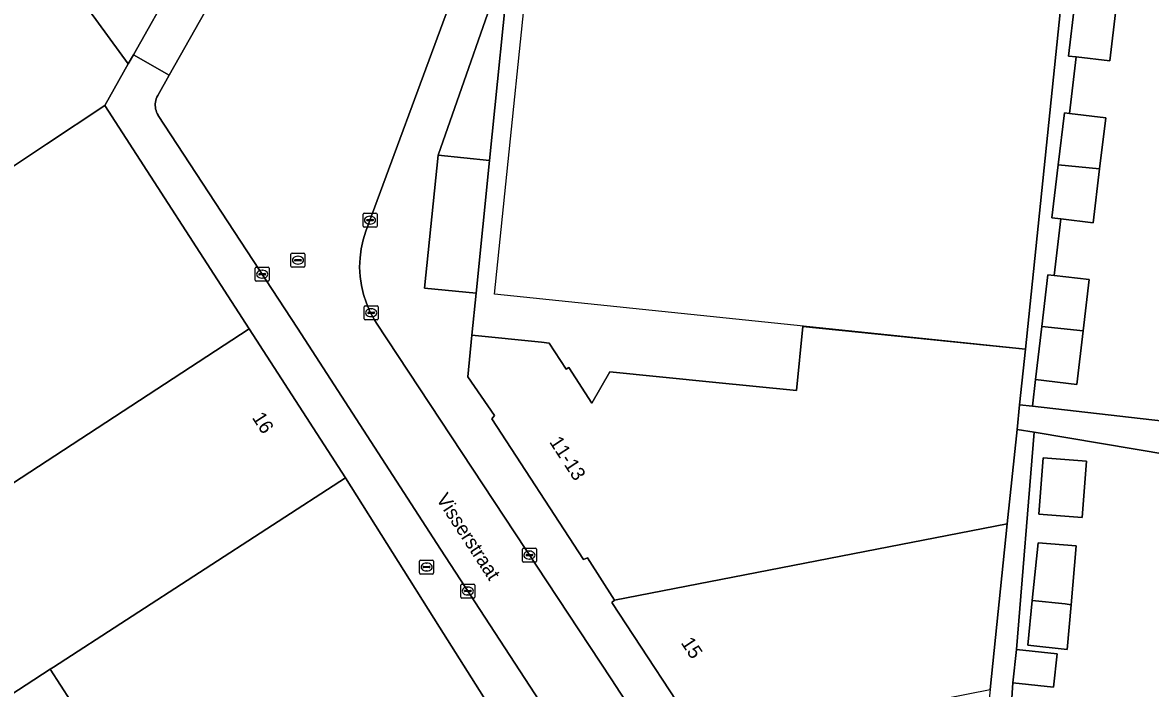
# Model space of a CAD drawing. Extents: x 160856 to 161310, y 384024 to 384878.
# Drawn here: x 161076.4 to 161157.1, y 384511.2 to 384558.9 of the extents above; entities that cross this region are included whole.
import ezdxf

# ---------------------------------------------------------------- set-up
doc = ezdxf.new("R2010")
doc.units = 0
for name, color, linetype in [('IMGEO_Brandkraan', 7, 'Continuous'), ('IMGEO_Erf', 7, 'Continuous'), ('IMGEO_Kolk', 7, 'Continuous'), ('IMGEO_Muur', 7, 'Continuous'), ('IMGEO_Openbare_ruimte_label', 7, 'Continuous'), ('IMGEO_Pand', 7, 'Continuous'), ('IMGEO_Pand_nummerreeks', 7, 'Continuous'), ('IMGEO_Pand_vergunning_verleend', 7, 'Continuous'), ('IMGEO_Parkeervlak_open', 7, 'Continuous'), ('IMGEO_Rijbaan_lokaal_open', 7, 'Continuous'), ('IMGEO_Rioolput', 7, 'Continuous'), ('IMGEO_Voetpad_open', 7, 'Continuous')]:
    doc.layers.add(name, color=color, linetype=linetype)

msp = doc.modelspace()

# ---------------------------------------------------------------- linework, layer by layer
at = {"layer": 'IMGEO_Brandkraan'}
for p, q in [((161104.842, 384519.474), (161104.842, 384520.326)), ((161104.917, 384520.4), (161105.769, 384520.4)), ((161105.33, 384520.18), (161105.355, 384520.18)), ((161105.843, 384520.326), (161105.843, 384519.474)), ((161105.769, 384519.4), (161104.917, 384519.4)), ((161105.101, 384519.894), (161105.101, 384519.906)), ((161105.539, 384519.857), (161105.141, 384519.857)), ((161105.144, 384519.943), (161105.542, 384519.943)), ((161105.353, 384519.62), (161105.328, 384519.62)), ((161105.585, 384519.906), (161105.585, 384519.894))]:
    msp.add_line(p, q, dxfattribs=at)
for points in [[(161104.842, 384519.474), (161104.842, 384520.326)], [(161104.917, 384520.4), (161105.769, 384520.4)], [(161105.843, 384520.326), (161105.843, 384519.474)], [(161105.769, 384519.4), (161104.917, 384519.4)]]:
    msp.add_lwpolyline(points, dxfattribs=at)
for centre, radius, start, end in [((161104.919, 384520.324), 0.0765, 91.55205, 178.44795), ((161104.919, 384520.324), 0.0765, 91.55205, 178.44795), ((161105.767, 384520.324), 0.0765, 1.55205, 88.44795), ((161105.767, 384520.324), 0.0765, 1.55205, 88.44795), ((161104.919, 384519.476), 0.0765, 181.55205, 268.44795), ((161104.919, 384519.476), 0.0765, 181.55205, 268.44795), ((161105.141, 384519.903), 0.0403, 85.87752, 175.75265), ((161105.138, 384519.893), 0.0366, 178.93798, 274.71019), ((161105.542, 384519.9), 0.043, 264.86636, 352.45326), ((161105.546, 384519.905), 0.0386, 1.73085, 96.63898), ((161105.767, 384519.476), 0.0765, 271.55205, 358.44795), ((161105.767, 384519.476), 0.0765, 271.55205, 358.44795)]:
    msp.add_arc(centre, radius, start, end, dxfattribs=at)
for centre, major_axis, ratio, start_param, end_param in [((161105.329, 384519.9), (-0.387, 0.002), 0.722429, 4.712389, 7.853982), ((161105.354, 384519.9), (-0.39, 0.002), 0.717154, 1.570796, 4.712389)]:
    msp.add_ellipse(centre, major_axis=major_axis, ratio=ratio, start_param=start_param, end_param=end_param, dxfattribs=at)
at = {"layer": 'IMGEO_Erf'}
for points in [[(161151.278, 384565.385), (161119.159, 384568.638), (161113.261, 384569.256), (161111.404, 384564.308), (161109.851, 384548.986), (161108.888, 384539.484), (161108.586, 384536.5), (161113.56, 384535.984), (161114.109, 384535.927), (161115.335, 384534.049), (161115.518, 384534.168), (161117.174, 384531.631), (161118.462, 384533.867), (161125.805, 384533.126), (161131.806, 384532.52), (161132.272, 384537.113), (161148.189, 384535.497)], [(161149.148, 384523.684), (161149.461, 384527.721), (161152.575, 384527.48), (161152.263, 384523.443)], [(161109.703, 384510.154), (161106.274, 384515.593), (161099.532, 384526.285), (161078.632, 384512.731), (161078.403, 384512.582), (161086.528, 384500), (161089.266, 384495.761), (161093.508, 384498.519), (161093.22, 384498.961), (161094.818, 384500), (161104.086, 384506.027), (161103.703, 384506.616), (161103.966, 384506.787), (161104.133, 384506.531)], [(161151.459, 384517.196), (161151.179, 384513.998), (161148.36, 384514.309), (161148.683, 384517.506), (161149.099, 384521.62), (161151.828, 384521.418)]]:
    msp.add_lwpolyline(points, close=True, dxfattribs=at)
for points in [[(161154.683, 384559.954), (161154.228, 384556.109), (161151.831, 384556.393), (161151.352, 384552.341), (161153.94, 384552.035), (161153.507, 384548.38), (161153.052, 384544.535), (161150.736, 384544.809), (161150.256, 384540.757), (161152.763, 384540.46), (161152.33, 384536.804), (161151.875, 384532.96), (161148.919, 384533.31), (161148.694, 384531.411), (161164.334, 384529.618)], [(161163.276, 384527.128), (161148.815, 384529.545), (161147.564, 384514.007), (161150.475, 384513.686), (161150.211, 384511.294), (161147.3, 384511.615), (161147.199, 384510.164), (161149.928, 384509.962), (161149.557, 384505.722), (161149.279, 384502.542), (161146.46, 384502.853), (161144.606, 384486.647), (161147.568, 384486.405), (161147.279, 384482.873), (161144.317, 384483.115), (161144.28, 384482.884), (161157.474, 384480.784)]]:
    msp.add_lwpolyline(points, dxfattribs=at)
at = {"layer": 'IMGEO_Kolk'}
for p, q in [((161100.794, 384544.292), (161100.794, 384545.144)), ((161100.869, 384545.218), (161101.721, 384545.218)), ((161101.795, 384545.144), (161101.795, 384544.292)), ((161101.053, 384544.712), (161101.053, 384544.724)), ((161101.491, 384544.675), (161101.093, 384544.675)), ((161101.096, 384544.761), (161101.494, 384544.761)), ((161101.305, 384544.438), (161101.28, 384544.438)), ((161101.282, 384544.998), (161101.307, 384544.998)), ((161101.537, 384544.724), (161101.537, 384544.712)), ((161101.721, 384544.218), (161100.869, 384544.218)), ((161093.078, 384540.423), (161093.078, 384541.275)), ((161093.153, 384541.349), (161094.005, 384541.349)), ((161093.566, 384541.129), (161093.591, 384541.129)), ((161094.079, 384541.275), (161094.079, 384540.423)), ((161094.005, 384540.349), (161093.153, 384540.349)), ((161093.337, 384540.843), (161093.337, 384540.855)), ((161093.775, 384540.806), (161093.377, 384540.806)), ((161093.38, 384540.892), (161093.778, 384540.892)), ((161093.589, 384540.569), (161093.564, 384540.569)), ((161093.821, 384540.855), (161093.821, 384540.843)), ((161100.877, 384537.666), (161100.877, 384538.518)), ((161100.952, 384538.592), (161101.804, 384538.592)), ((161101.136, 384538.086), (161101.136, 384538.098)), ((161101.574, 384538.049), (161101.176, 384538.049)), ((161101.179, 384538.135), (161101.577, 384538.135)), ((161101.365, 384538.372), (161101.39, 384538.372)), ((161101.62, 384538.098), (161101.62, 384538.086)), ((161101.878, 384538.518), (161101.878, 384537.666)), ((161101.804, 384537.592), (161100.952, 384537.592)), ((161101.388, 384537.812), (161101.363, 384537.812)), ((161112.2, 384520.328), (161112.2, 384521.18)), ((161112.275, 384521.254), (161113.127, 384521.254)), ((161112.688, 384521.034), (161112.713, 384521.034)), ((161113.201, 384521.18), (161113.201, 384520.328)), ((161113.127, 384520.254), (161112.275, 384520.254)), ((161112.459, 384520.748), (161112.459, 384520.76)), ((161112.897, 384520.711), (161112.499, 384520.711)), ((161112.502, 384520.797), (161112.9, 384520.797)), ((161112.711, 384520.474), (161112.686, 384520.474)), ((161112.943, 384520.76), (161112.943, 384520.748)), ((161107.791, 384517.756), (161107.791, 384518.608)), ((161107.866, 384518.682), (161108.718, 384518.682)), ((161108.792, 384518.608), (161108.792, 384517.756)), ((161108.05, 384518.176), (161108.05, 384518.188)), ((161108.488, 384518.139), (161108.09, 384518.139)), ((161108.093, 384518.225), (161108.491, 384518.225)), ((161108.302, 384517.902), (161108.277, 384517.902)), ((161108.279, 384518.462), (161108.304, 384518.462)), ((161108.534, 384518.188), (161108.534, 384518.176)), ((161108.718, 384517.682), (161107.866, 384517.682))]:
    msp.add_line(p, q, dxfattribs=at)
for points in [[(161100.794, 384544.292), (161100.794, 384545.144)], [(161100.869, 384545.218), (161101.721, 384545.218)], [(161101.795, 384545.144), (161101.795, 384544.292)], [(161101.721, 384544.218), (161100.869, 384544.218)], [(161093.078, 384540.423), (161093.078, 384541.275)], [(161093.153, 384541.349), (161094.005, 384541.349)], [(161094.079, 384541.275), (161094.079, 384540.423)], [(161094.005, 384540.349), (161093.153, 384540.349)], [(161100.877, 384537.666), (161100.877, 384538.518)], [(161100.952, 384538.592), (161101.804, 384538.592)], [(161101.878, 384538.518), (161101.878, 384537.666)], [(161101.804, 384537.592), (161100.952, 384537.592)], [(161112.2, 384520.328), (161112.2, 384521.18)], [(161112.275, 384521.254), (161113.127, 384521.254)], [(161113.201, 384521.18), (161113.201, 384520.328)], [(161113.127, 384520.254), (161112.275, 384520.254)], [(161107.791, 384517.756), (161107.791, 384518.608)], [(161107.866, 384518.682), (161108.718, 384518.682)], [(161108.792, 384518.608), (161108.792, 384517.756)], [(161108.718, 384517.682), (161107.866, 384517.682)]]:
    msp.add_lwpolyline(points, dxfattribs=at)
for centre, radius, start, end in [((161100.871, 384545.142), 0.0765, 91.55205, 178.44795), ((161100.871, 384545.142), 0.0765, 91.55205, 178.44795), ((161101.719, 384545.142), 0.0765, 1.55205, 88.44795), ((161101.719, 384545.142), 0.0765, 1.55205, 88.44795), ((161101.093, 384544.721), 0.0403, 85.87752, 175.75265), ((161101.09, 384544.711), 0.0366, 178.93798, 274.71019), ((161101.494, 384544.718), 0.043, 264.86636, 352.45326), ((161101.498, 384544.723), 0.0386, 1.73085, 96.63898), ((161100.871, 384544.294), 0.0765, 181.55205, 268.44795), ((161100.871, 384544.294), 0.0765, 181.55205, 268.44795), ((161101.719, 384544.294), 0.0765, 271.55205, 358.44795), ((161101.719, 384544.294), 0.0765, 271.55205, 358.44795), ((161093.155, 384541.273), 0.0765, 91.55205, 178.44795), ((161093.155, 384541.273), 0.0765, 91.55205, 178.44795), ((161094.003, 384541.273), 0.0765, 1.55205, 88.44795), ((161094.003, 384541.273), 0.0765, 1.55205, 88.44795), ((161093.155, 384540.425), 0.0765, 181.55205, 268.44795), ((161093.155, 384540.425), 0.0765, 181.55205, 268.44795), ((161093.377, 384540.852), 0.0403, 85.87752, 175.75265), ((161093.374, 384540.842), 0.0366, 178.93798, 274.71019), ((161093.778, 384540.849), 0.043, 264.86636, 352.45326), ((161093.782, 384540.854), 0.0386, 1.73085, 96.63898), ((161094.003, 384540.425), 0.0765, 271.55205, 358.44795), ((161094.003, 384540.425), 0.0765, 271.55205, 358.44795), ((161100.954, 384538.516), 0.0765, 91.55205, 178.44795), ((161100.954, 384538.516), 0.0765, 91.55205, 178.44795), ((161101.176, 384538.095), 0.0403, 85.87752, 175.75265), ((161101.173, 384538.085), 0.0366, 178.93798, 274.71019), ((161101.577, 384538.092), 0.043, 264.86636, 352.45326), ((161101.581, 384538.097), 0.0386, 1.73085, 96.63898), ((161101.802, 384538.516), 0.0765, 1.55205, 88.44795), ((161101.802, 384538.516), 0.0765, 1.55205, 88.44795), ((161100.954, 384537.668), 0.0765, 181.55205, 268.44795), ((161100.954, 384537.668), 0.0765, 181.55205, 268.44795), ((161101.802, 384537.668), 0.0765, 271.55205, 358.44795), ((161101.802, 384537.668), 0.0765, 271.55205, 358.44795), ((161112.277, 384521.178), 0.0765, 91.55205, 178.44795), ((161112.277, 384521.178), 0.0765, 91.55205, 178.44795), ((161113.125, 384521.178), 0.0765, 1.55205, 88.44795), ((161113.125, 384521.178), 0.0765, 1.55205, 88.44795), ((161112.277, 384520.33), 0.0765, 181.55205, 268.44795), ((161112.277, 384520.33), 0.0765, 181.55205, 268.44795), ((161112.499, 384520.757), 0.0403, 85.87752, 175.75265), ((161112.496, 384520.747), 0.0366, 178.93798, 274.71019), ((161112.9, 384520.754), 0.043, 264.86636, 352.45326), ((161112.904, 384520.759), 0.0386, 1.73085, 96.63898), ((161113.125, 384520.33), 0.0765, 271.55205, 358.44795), ((161113.125, 384520.33), 0.0765, 271.55205, 358.44795), ((161107.868, 384518.606), 0.0765, 91.55205, 178.44795), ((161107.868, 384518.606), 0.0765, 91.55205, 178.44795), ((161108.716, 384518.606), 0.0765, 1.55205, 88.44795), ((161108.716, 384518.606), 0.0765, 1.55205, 88.44795), ((161107.868, 384517.758), 0.0765, 181.55205, 268.44795), ((161107.868, 384517.758), 0.0765, 181.55205, 268.44795), ((161108.09, 384518.185), 0.0403, 85.87752, 175.75265), ((161108.087, 384518.175), 0.0366, 178.93798, 274.71019), ((161108.491, 384518.182), 0.043, 264.86636, 352.45326), ((161108.495, 384518.187), 0.0386, 1.73085, 96.63898), ((161108.716, 384517.758), 0.0765, 271.55205, 358.44795), ((161108.716, 384517.758), 0.0765, 271.55205, 358.44795)]:
    msp.add_arc(centre, radius, start, end, dxfattribs=at)
for centre, major_axis, ratio, start_param, end_param in [((161101.281, 384544.718), (-0.387, 0.002), 0.722429, 4.712389, 7.853982), ((161101.306, 384544.718), (-0.39, 0.002), 0.717154, 1.570796, 4.712389), ((161093.565, 384540.849), (-0.387, 0.002), 0.722429, 4.712389, 7.853982), ((161093.59, 384540.849), (-0.39, 0.002), 0.717154, 1.570796, 4.712389), ((161101.364, 384538.092), (-0.387, 0.002), 0.722429, 4.712389, 7.853982), ((161101.389, 384538.092), (-0.39, 0.002), 0.717154, 1.570796, 4.712389), ((161112.687, 384520.754), (-0.387, 0.002), 0.722429, 4.712389, 7.853982), ((161112.712, 384520.754), (-0.39, 0.002), 0.717154, 1.570796, 4.712389), ((161108.278, 384518.182), (-0.387, 0.002), 0.722429, 4.712389, 7.853982), ((161108.303, 384518.182), (-0.39, 0.002), 0.717154, 1.570796, 4.712389)]:
    msp.add_ellipse(centre, major_axis=major_axis, ratio=ratio, start_param=start_param, end_param=end_param, dxfattribs=at)
at = {"layer": 'IMGEO_Muur'}
msp.add_lwpolyline([(161099.532, 384526.285), (161106.274, 384515.593)], dxfattribs=at)
at = {"layer": 'IMGEO_Pand'}
for points in [[(161154.683, 384559.954), (161151.722, 384560.255), (161151.272, 384556.459), (161151.831, 384556.393), (161154.228, 384556.109)], [(161061.847, 384516.849), (161092.65, 384536.939), (161082.319, 384552.931), (161078.154, 384550.165), (161074.251, 384547.573), (161050.778, 384531.991)], [(161153.94, 384552.035), (161151.352, 384552.341), (161150.984, 384552.385), (161150.546, 384548.681), (161153.507, 384548.38)], [(161153.507, 384548.38), (161150.546, 384548.681), (161150.096, 384544.885), (161150.736, 384544.809), (161153.052, 384544.535)], [(161152.763, 384540.46), (161150.256, 384540.757), (161149.807, 384540.81), (161149.369, 384537.105), (161152.33, 384536.804)], [(161147.778, 384531.516), (161148.189, 384535.497), (161132.272, 384537.113), (161131.806, 384532.52), (161125.805, 384533.126), (161118.462, 384533.867), (161117.174, 384531.631), (161115.518, 384534.168), (161115.335, 384534.049), (161114.109, 384535.927), (161113.56, 384535.984), (161108.586, 384536.5), (161108.284, 384533.515), (161110.201, 384530.752), (161110.014, 384530.492), (161116.568, 384520.434), (161116.865, 384520.568), (161118.791, 384517.525), (161146.897, 384522.997), (161147.595, 384529.749)], [(161152.33, 384536.804), (161149.369, 384537.105), (161148.919, 384533.31), (161151.875, 384532.96)], [(161099.532, 384526.285), (161092.65, 384536.939), (161061.847, 384516.849), (161064.523, 384513.188), (161069.287, 384506.671), (161069.859, 384507.042), (161078.403, 384512.582), (161078.632, 384512.731)], [(161152.575, 384527.48), (161149.461, 384527.721), (161149.148, 384523.684), (161152.263, 384523.443)], [(161118.791, 384517.525), (161118.6, 384517.368), (161125.289, 384507.167), (161139.008, 384509.838), (161145.671, 384511.135), (161146.897, 384522.997)], [(161148.683, 384517.506), (161151.033, 384517.267), (161151.459, 384517.196), (161151.828, 384521.418), (161149.099, 384521.62)], [(161148.683, 384517.506), (161148.36, 384514.309), (161151.179, 384513.998), (161151.459, 384517.196), (161151.033, 384517.267)], [(161147.564, 384514.007), (161147.3, 384511.615), (161150.211, 384511.294), (161150.475, 384513.686)], [(161086.528, 384500), (161078.403, 384512.582), (161069.859, 384507.042), (161070.066, 384506.722), (161074.406, 384500), (161086.57, 384481.163), (161095.125, 384486.687), (161089.266, 384495.761)]]:
    msp.add_lwpolyline(points, close=True, dxfattribs=at)
at = {"layer": 'IMGEO_Pand_vergunning_verleend'}
msp.add_lwpolyline([(161110.191, 384539.424), (161113.28, 384569.312), (161151.278, 384565.385), (161148.189, 384535.497)], close=True, dxfattribs=at)
at = {"layer": 'IMGEO_Parkeervlak_open'}
for points in [[(161129.988, 384500), (161125.289, 384507.167), (161118.6, 384517.368), (161118.791, 384517.525), (161116.865, 384520.568), (161116.568, 384520.434), (161110.014, 384530.492), (161110.201, 384530.752), (161108.284, 384533.515), (161108.586, 384536.5), (161108.888, 384539.484), (161105.202, 384539.856), (161106.17, 384549.359), (161111.404, 384564.308), (161113.261, 384569.256), (161118.045, 384583.164), (161121.366, 384592.819), (161123.534, 384599.122), (161124.003, 384603.832), (161125.354, 384617.415)], [(161106.734, 384559.483), (161101.005, 384543.933), (161100.805, 384543.305), (161100.662, 384542.663), (161100.578, 384542.01), (161100.552, 384541.352), (161100.584, 384540.694), (161100.676, 384540.042), (161100.825, 384539.4), (161101.031, 384538.775), (161101.292, 384538.17), (161101.606, 384537.591), (161101.766, 384537.337), (161118.543, 384511.891), (161126.296, 384500)], [(161106.333, 384521.187), (161096.1, 384536.996), (161086.143, 384552.216), (161086.131, 384552.234), (161086.071, 384552.34), (161086.021, 384552.451), (161085.981, 384552.566), (161085.951, 384552.684), (161085.932, 384552.805), (161085.924, 384552.926), (161085.926, 384553.048), (161085.94, 384553.169), (161085.964, 384553.288), (161085.999, 384553.405), (161086.044, 384553.518), (161086.099, 384553.627), (161086.931, 384555.099), (161084.359, 384556.55), (161083.992, 384555.898), (161082.319, 384552.931), (161092.65, 384536.939), (161099.532, 384526.285), (161106.274, 384515.593), (161109.703, 384510.154)], [(161147.548, 384467.735), (161146.601, 384468.302), (161145.038, 384469.237), (161143.348, 384470.277), (161140.555, 384472.281), (161137.951, 384474.526), (161135.559, 384476.994), (161133.535, 384479.496), (161133.397, 384479.667), (161120.155, 384500), (161106.333, 384521.187)]]:
    msp.add_lwpolyline(points, dxfattribs=at)
for points in [[(161066.613, 384557.83), (161074.251, 384547.573), (161078.154, 384550.165), (161082.319, 384552.931), (161083.992, 384555.898), (161076.965, 384565.538)], [(161108.888, 384539.484), (161109.851, 384548.986), (161106.17, 384549.359), (161105.202, 384539.856)]]:
    msp.add_lwpolyline(points, close=True, dxfattribs=at)
at = {"layer": 'IMGEO_Rijbaan_lokaal_open'}
msp.add_lwpolyline([(161074.987, 384573.785), (161061.858, 384564.216), (161066.613, 384557.83), (161076.965, 384565.538), (161083.992, 384555.898), (161084.359, 384556.55), (161087.296, 384561.759), (161091.331, 384568.917), (161090.784, 384569.226), (161085.386, 384565.183), (161083.895, 384567.258), (161083.142, 384566.717), (161081.654, 384568.788), (161081.228, 384568.49), (161079.698, 384570.692), (161079.104, 384570.239), (161077.575, 384572.29), (161076.629, 384571.551)], close=True, dxfattribs=at)
for points in [[(161089.873, 384560.302), (161086.931, 384555.099), (161086.099, 384553.627), (161086.044, 384553.518), (161085.999, 384553.405), (161085.964, 384553.288), (161085.94, 384553.169), (161085.926, 384553.048), (161085.924, 384552.926), (161085.932, 384552.805), (161085.951, 384552.684), (161085.981, 384552.566), (161086.021, 384552.451), (161086.071, 384552.34), (161086.131, 384552.234), (161086.143, 384552.216), (161096.1, 384536.996), (161106.333, 384521.187), (161120.155, 384500)], [(161126.296, 384500), (161118.543, 384511.891), (161101.766, 384537.337), (161101.606, 384537.591), (161101.292, 384538.17), (161101.031, 384538.775), (161100.825, 384539.4), (161100.676, 384540.042), (161100.584, 384540.694), (161100.552, 384541.352), (161100.578, 384542.01), (161100.662, 384542.663), (161100.805, 384543.305), (161101.005, 384543.933), (161106.734, 384559.483)]]:
    msp.add_lwpolyline(points, dxfattribs=at)
at = {"layer": 'IMGEO_Rioolput'}
for p, q in [((161095.637, 384541.425), (161095.637, 384542.277)), ((161095.712, 384542.351), (161096.564, 384542.351)), ((161096.125, 384542.131), (161096.15, 384542.131)), ((161096.638, 384542.277), (161096.638, 384541.425)), ((161096.564, 384541.351), (161095.712, 384541.351)), ((161095.896, 384541.845), (161095.896, 384541.857)), ((161096.334, 384541.808), (161095.936, 384541.808)), ((161095.939, 384541.894), (161096.337, 384541.894)), ((161096.148, 384541.571), (161096.123, 384541.571)), ((161096.38, 384541.857), (161096.38, 384541.845))]:
    msp.add_line(p, q, dxfattribs=at)
for points in [[(161095.637, 384541.425), (161095.637, 384542.277)], [(161095.712, 384542.351), (161096.564, 384542.351)], [(161096.638, 384542.277), (161096.638, 384541.425)], [(161096.564, 384541.351), (161095.712, 384541.351)]]:
    msp.add_lwpolyline(points, dxfattribs=at)
for centre, radius, start, end in [((161095.714, 384542.275), 0.0765, 91.55205, 178.44795), ((161095.714, 384542.275), 0.0765, 91.55205, 178.44795), ((161096.562, 384542.275), 0.0765, 1.55205, 88.44795), ((161096.562, 384542.275), 0.0765, 1.55205, 88.44795), ((161095.714, 384541.427), 0.0765, 181.55205, 268.44795), ((161095.714, 384541.427), 0.0765, 181.55205, 268.44795), ((161095.936, 384541.854), 0.0403, 85.87752, 175.75265), ((161095.933, 384541.844), 0.0366, 178.93798, 274.71019), ((161096.337, 384541.851), 0.043, 264.86636, 352.45326), ((161096.341, 384541.856), 0.0386, 1.73085, 96.63898), ((161096.562, 384541.427), 0.0765, 271.55205, 358.44795), ((161096.562, 384541.427), 0.0765, 271.55205, 358.44795)]:
    msp.add_arc(centre, radius, start, end, dxfattribs=at)
for centre, major_axis, ratio, start_param, end_param in [((161096.124, 384541.851), (-0.387, 0.002), 0.722429, 4.712389, 7.853982), ((161096.149, 384541.851), (-0.39, 0.002), 0.717154, 1.570796, 4.712389)]:
    msp.add_ellipse(centre, major_axis=major_axis, ratio=ratio, start_param=start_param, end_param=end_param, dxfattribs=at)
at = {"layer": 'IMGEO_Voetpad_open'}
msp.add_lwpolyline([(161151.278, 384565.385), (161148.189, 384535.497), (161147.778, 384531.516), (161148.694, 384531.411), (161148.919, 384533.31), (161149.369, 384537.105), (161149.807, 384540.81), (161150.256, 384540.757), (161150.736, 384544.809), (161150.096, 384544.885), (161150.546, 384548.681), (161150.984, 384552.385), (161151.352, 384552.341), (161151.831, 384556.393), (161151.272, 384556.459), (161151.722, 384560.255)], dxfattribs=at)
for points in [[(161106.17, 384549.359), (161109.851, 384548.986), (161111.404, 384564.308)], [(161089.873, 384560.302), (161087.296, 384561.759), (161084.359, 384556.55), (161086.931, 384555.099)], [(161166.718, 384529.376), (161164.334, 384529.618), (161148.694, 384531.411), (161147.778, 384531.516), (161147.595, 384529.749), (161148.815, 384529.545), (161163.276, 384527.128), (161166.789, 384526.546), (161169.167, 384526.152), (161171.326, 384525.794), (161171.692, 384528.87)], [(161147.199, 384510.164), (161147.3, 384511.615), (161147.564, 384514.007), (161148.815, 384529.545), (161147.595, 384529.749), (161146.897, 384522.997), (161145.671, 384511.135), (161144.52, 384500), (161144.181, 384496.717), (161143.676, 384491.742), (161142.816, 384483.117), (161144.28, 384482.884), (161144.317, 384483.115), (161144.606, 384486.647), (161146.46, 384502.853), (161146.778, 384506.004)]]:
    msp.add_lwpolyline(points, close=True, dxfattribs=at)

# ---------------------------------------------------------------- texts
at = {"layer": 'IMGEO_Openbare_ruimte_label'}
msp.add_text('Visserstraat', height=1, rotation=303.08631, dxfattribs=at).set_placement((161105.998, 384524.767))
at = {"layer": 'IMGEO_Pand_nummerreeks'}
for s, rotation, p in [('16', 302.94486, (161092.821, 384530.588)), ('11-13', 303.0881, (161114.091, 384528.851)), ('15', 303.25366, (161123.508, 384514.48))]:
    msp.add_text(s, height=1, rotation=rotation, dxfattribs=at).set_placement(p)

doc.saveas('drawing.dxf')
